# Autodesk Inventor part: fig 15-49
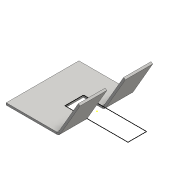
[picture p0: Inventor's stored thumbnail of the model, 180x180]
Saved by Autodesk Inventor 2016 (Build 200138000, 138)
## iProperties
Created: 2015-07
Part Number: fig 15-49
Material: Generic
Document SubType Name: Sheet Metal
Designer: Sandeep
Density: 1 g/cm^3
Sheet Metal Rule: Default_mm
Appearance: Default
Author: Sandeep
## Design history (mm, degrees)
node "Face1"
  sketch "Sketch1"
    geometry: L1 (-12.609, 8.313)-(0, 8.313); L2 (0, 8.313)-(0, -9.006); L3 (0, -9.006)-(-12.609, -9.006); L4 (-12.609, -9.006)-(-12.609, 8.313); 1 further point
    constraints: 8 end point, 2 parallel, 1 horizontal, 1 perpendicular
node "Flange1"
sketch "Sketch3"
  geometry: L1 (9.998, 1.795)-(-5.034, 1.795); L2 (-5.034, 1.795)-(-5.034, -2.633); L3 (-5.034, -2.633)-(9.998, -2.633); L4 (9.998, -2.633)-(9.998, 1.795); 1 further point
  constraints: 8 end point, 2 parallel, 1 horizontal, 1 perpendicular
cut "Cut1" sketch "Sketch3" dims "d11" = 0.5 (= Thickness), "d12" = 0
body "Solid1"
face "Plate1" dims "Thickness" = 0.5
sketch "Sketch2"
  geometry: L1 through (-8.66, 0) direction (1, 0); L2 through (0, 5) direction (0, 1); L3 (0, 10)-(-17.319, 10); L4 (-17.319, 10)-(-17.319, 0)
  constraints: 6 end point, 1 horizontal, 1 perpendicular, 1 vertical
face "Plate2" dims "d1" = 0.5 (= BendReliefWidth), "d2" = 0.25 (= BendReliefDepth), "d3" = 1 (= MinimumRemnant), "d4" = 0.5 (= BendRadius), "d5" = 10, "d6" = 60 deg, "d7" = 0.5 (= BendRadius), "d8" = 2 (= CornerReliefSize), "d9" = 0.5 (= GapSize), "d10" = 0.5 (= JacobiRadiusSize), "SeamGap" = 0.01, "Thickness" = 0.5
bend "Bend1" dims "d1" = 0.5 (= BendReliefWidth), "d2" = 0.25 (= BendReliefDepth), "d3" = 1 (= MinimumRemnant), "d4" = 0.5 (= BendRadius), "d5" = 10, "d6" = 60 deg, "d7" = 0.5 (= BendRadius), "SeamGap" = 0.01, "Thickness" = 0.5
feature "Corner1" dims "d5" = 10, "d6" = 60 deg, "d8" = 2 (= CornerReliefSize), "d9" = 0.5 (= GapSize), "d10" = 0.5 (= JacobiRadiusSize)
other parameters: "BendRadius" = 0.5 (= Thickness), "BendReliefWidth" = 0.5 (= Thickness), "BendReliefDepth" = 0.25 (= 0.5 x Thickness), "CornerReliefSize" = 2 (= 4 x Thickness), "MinimumRemnant" = 1 (= 2 x Thickness), "TransitionRadius" = 0.5 (= BendRadius), "JacobiRadiusSize" = 0.5 (= BendRadius), "GapSize" = 0.5 (= Thickness), "d0" = 0.5 (= BendRadius)
